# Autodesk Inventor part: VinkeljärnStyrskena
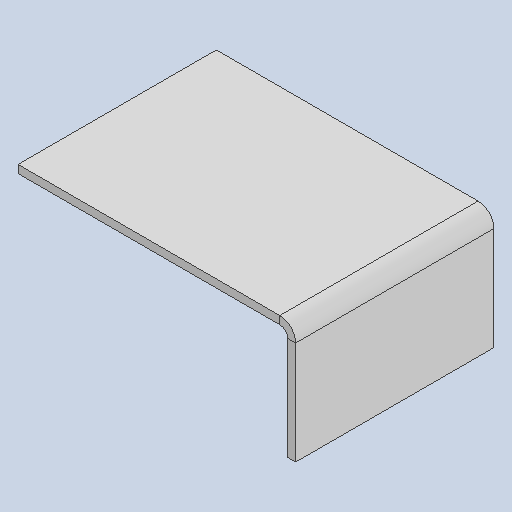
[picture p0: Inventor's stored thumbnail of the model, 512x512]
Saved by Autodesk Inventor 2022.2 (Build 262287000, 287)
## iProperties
Created: 2019-07
Part Number: VinkeljärnStyrskena
Material: Generic
Document SubType Name: Sheet Metal
Designer: cl
Density: 1 g/cm^3
Sheet Metal Rule: Default_mm
Appearance: Default
Author: cl
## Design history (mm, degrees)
node "Face1"
  sketch "Sketch2"
    geometry: L1 (0, 0)-(140, 0); L2 (140, 0)-(140, -100); L3 (140, -100)-(0, -100); L4 (0, -100)-(0, 0)
    constraints: 8 end point, 2 parallel, 1 horizontal, 1 perpendicular
    dimensions: "d0" = 140 distance of L2.end L3.end; "d1" = 100 distance of L1.end L2.end
node "Flange1"
body "Solid1"
face "Plate1" dims "d2" = 4 (= Thickness)
sketch "Sketch3"
  geometry: L1 through (0, 50) direction (0, -1); L2 through (30, 0) direction (1, 0); L3 (60, 0)-(60, 100); L4 (60, 100)-(0, 100)
  constraints: 6 end point, 1 horizontal, 1 perpendicular, 1 vertical
face "Plate2" dims "d2" = 4 (= Thickness), "d3" = 4 (= BendReliefWidth), "d4" = 2 (= BendReliefDepth), "d5" = 8 (= MinimumRemnant), "d6" = 4 (= TransitionRadius), "d7" = 60, "d8" = -90 deg, "d9" = 4 (= BendRadius), "d10" = 16 (= CornerReliefSize), "d11" = 4 (= GapSize), "d12" = 4 (= JacobiRadiusSize), "SeamGap" = 0.01
bend "Bend1" dims "d2" = 4 (= Thickness), "d3" = 4 (= BendReliefWidth), "d4" = 2 (= BendReliefDepth), "d5" = 8 (= MinimumRemnant), "d6" = 4 (= TransitionRadius), "d7" = 60, "d8" = -90 deg, "d9" = 4 (= BendRadius), "SeamGap" = 0.01
feature "Corner1" dims "d7" = 60, "d8" = -90 deg, "d10" = 16 (= CornerReliefSize), "d11" = 4 (= GapSize), "d12" = 4 (= JacobiRadiusSize)
other parameters: "Thickness" = 4 (derived), "KFactor" = 4.4, "BendRadius" = 4 (= Thickness), "BendReliefWidth" = 4 (= Thickness), "BendReliefDepth" = 2 (= 0.5 x Thickness), "CornerReliefSize" = 16 (= 4 x Thickness), "MinimumRemnant" = 8 (= 2 x Thickness), "TransitionRadius" = 4 (= BendRadius), "JacobiRadiusSize" = 4 (= BendRadius), "GapSize" = 4 (= Thickness)
